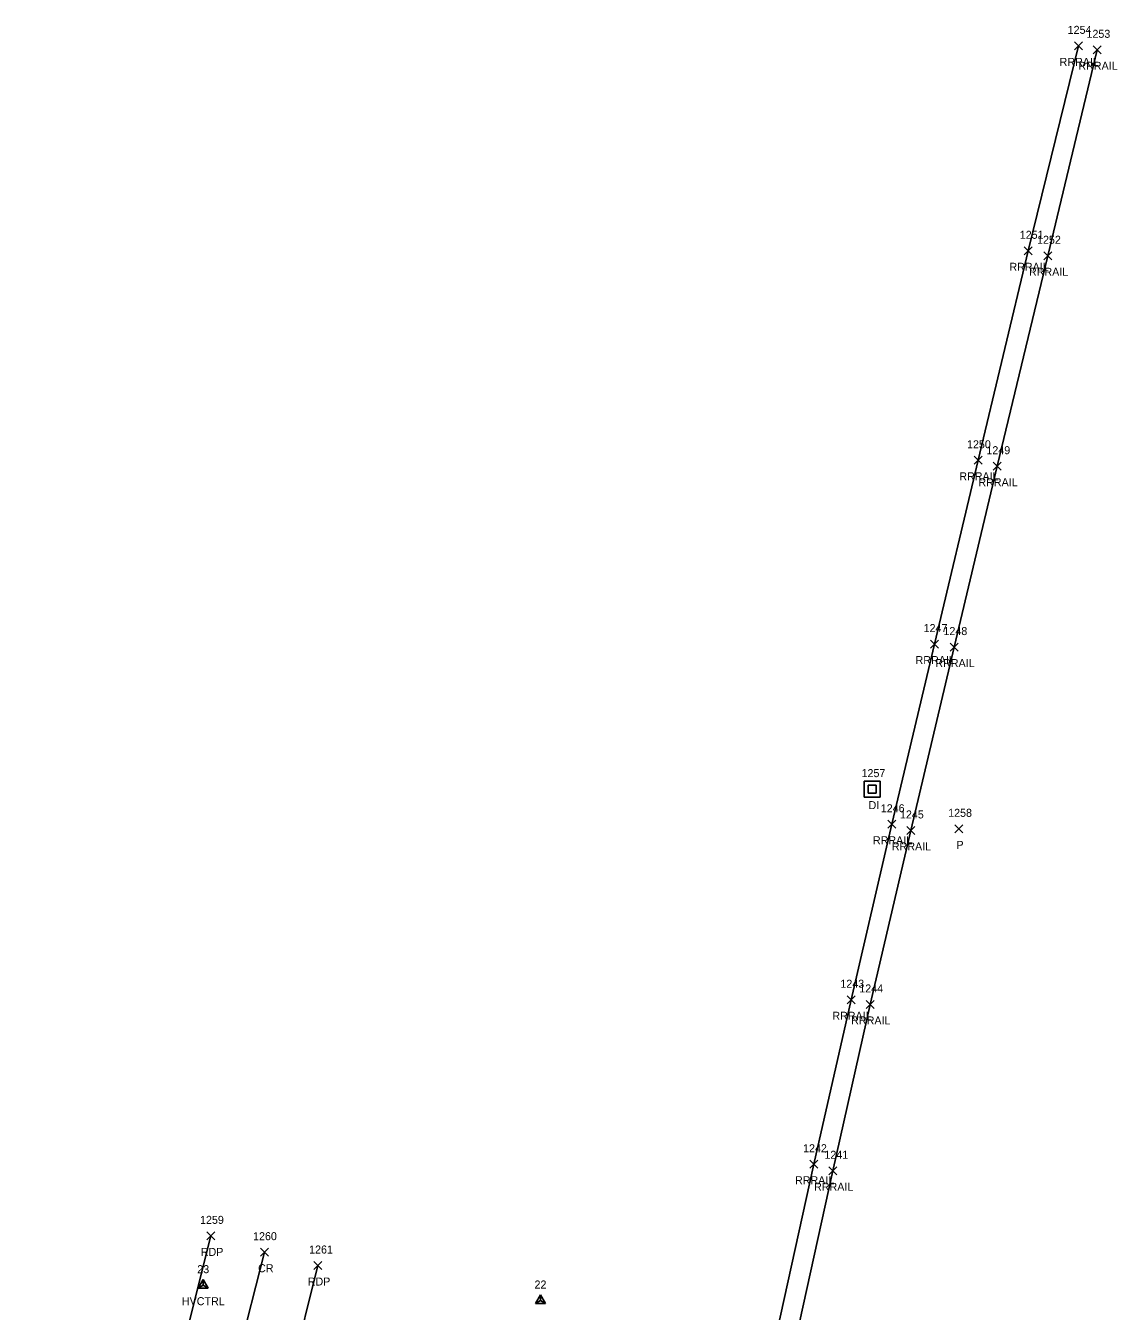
# Model space of a CAD drawing. Extents: x 1754529 to 1755810, y 621660 to 624656.
# Drawn here: x 1755537 to 1755809.8, y 624334.6 to 624655.8 of the extents above; entities that cross this region are included whole.
import ezdxf

# ---------------------------------------------------------------- set-up
doc = ezdxf.new("R2010")
doc.units = 0
for name, color, linetype in [('C_A', 7, 'Continuous'), ('C_I', 7, 'Continuous'), ('CPSM', 7, 'Continuous'), ('D_A', 7, 'Continuous'), ('D_I', 7, 'Continuous'), ('D_TIC', 7, 'Continuous'), ('DS', 7, 'Continuous'), ('Level 14', 7, 'Continuous'), ('P_A', 7, 'Continuous'), ('P_I', 7, 'Continuous'), ('PET', 7, 'Continuous'), ('PRC', 7, 'Continuous'), ('R_A', 7, 'Continuous'), ('R_I', 7, 'Continuous'), ('R_TIC', 7, 'Continuous'), ('RR', 7, 'Continuous')]:
    doc.layers.add(name, color=color, linetype=linetype)

msp = doc.modelspace()

# ---------------------------------------------------------------- linework, layer by layer
at = {"layer": 'CPSM'}
for p, q in [((1755580.07, 624340.36), (1755581.32, 624342.53)), ((1755582.57, 624340.36), (1755581.32, 624342.53)), ((1755581.32, 624341.08), (1755581.32, 624342.53)), ((1755580.07, 624340.36), (1755581.32, 624341.08)), ((1755580.07, 624340.36), (1755582.57, 624340.36)), ((1755581.32, 624341.08), (1755581.32, 624341.08)), ((1755581.32, 624341.08), (1755582.57, 624340.36)), ((1755664.34, 624336.53), (1755665.59, 624338.69)), ((1755664.34, 624336.53), (1755665.59, 624337.25)), ((1755664.34, 624336.53), (1755666.84, 624336.53)), ((1755666.84, 624336.53), (1755665.59, 624338.69)), ((1755665.59, 624337.25), (1755665.59, 624338.69)), ((1755665.59, 624337.25), (1755665.59, 624337.25)), ((1755665.59, 624337.25), (1755666.84, 624336.53))]:
    msp.add_line(p, q, dxfattribs=at)
at = {"layer": 'D_TIC'}
for points in [[(1755769.2, 624454.1), (1755771.2, 624456.1)], [(1755771.2, 624454.1), (1755769.2, 624456.1)]]:
    msp.add_lwpolyline(points, dxfattribs=at)
at = {"layer": 'DS'}
for p, q in [((1755746.54, 624467.02), (1755750.54, 624467.02)), ((1755746.54, 624463.02), (1755746.54, 624467.02)), ((1755747.54, 624464.02), (1755747.54, 624466.02)), ((1755747.54, 624466.02), (1755749.54, 624466.02)), ((1755748.54, 624465.02), (1755748.54, 624465.02)), ((1755748.54, 624465.02), (1755748.54, 624465.02)), ((1755749.54, 624466.02), (1755749.54, 624464.02)), ((1755750.54, 624467.02), (1755750.54, 624463.02)), ((1755750.54, 624463.02), (1755746.54, 624463.02)), ((1755749.54, 624464.02), (1755747.54, 624464.02))]:
    msp.add_line(p, q, dxfattribs=at)
at = {"layer": 'Level 14'}
for points in [[(1755582.24, 624352.4), (1755584.24, 624354.4)], [(1755584.24, 624352.4), (1755582.24, 624354.4)], [(1755595.62, 624348.32), (1755597.62, 624350.32)], [(1755597.62, 624348.32), (1755595.62, 624350.32)], [(1755608.98, 624344.99), (1755610.98, 624346.99)], [(1755610.98, 624344.99), (1755608.98, 624346.99)]]:
    msp.add_lwpolyline(points, dxfattribs=at)
at = {"layer": 'PET'}
for points in [[(1755583.24, 624353.4), (1755570.27, 624301.63), (1755560.22, 624258.14), (1755548.1, 624200.26), (1755536.97, 624143.24)], [(1755609.98, 624345.99), (1755597.12, 624294.33), (1755586.94, 624249.39), (1755575.43, 624196.55), (1755564.19, 624138.53)]]:
    msp.add_lwpolyline(points, dxfattribs=at)
at = {"layer": 'PRC'}
msp.add_lwpolyline([(1755596.62, 624349.32), (1755583.45, 624297.71), (1755573.49, 624253.54), (1755562.13, 624198.27), (1755550.9, 624141.51)], dxfattribs=at)
at = {"layer": 'R_TIC'}
for points in [[(1755799.05, 624649.73), (1755801.05, 624651.73)], [(1755801.05, 624649.73), (1755799.05, 624651.73)], [(1755803.75, 624648.74), (1755805.75, 624650.74)], [(1755805.75, 624648.74), (1755803.75, 624650.74)], [(1755786.52, 624598.52), (1755788.52, 624600.52)], [(1755788.52, 624598.52), (1755786.52, 624600.52)], [(1755791.4, 624597.28), (1755793.4, 624599.28)], [(1755793.4, 624597.28), (1755791.4, 624599.28)], [(1755773.99, 624546.18), (1755775.99, 624548.18)], [(1755775.99, 624546.18), (1755773.99, 624548.18)], [(1755778.76, 624544.7), (1755780.76, 624546.7)], [(1755780.76, 624544.7), (1755778.76, 624546.7)], [(1755763.06, 624500.26), (1755765.06, 624502.26)], [(1755765.06, 624500.26), (1755763.06, 624502.26)], [(1755768.01, 624499.51), (1755770.01, 624501.51)], [(1755770.01, 624499.51), (1755768.01, 624501.51)], [(1755752.41, 624455.24), (1755754.41, 624457.24)], [(1755754.41, 624455.24), (1755752.41, 624457.24)], [(1755757.14, 624453.7), (1755759.14, 624455.7)], [(1755759.14, 624453.7), (1755757.14, 624455.7)], [(1755742.26, 624411.4), (1755744.26, 624413.4)], [(1755744.26, 624411.4), (1755742.26, 624413.4)], [(1755746.98, 624410.22), (1755748.98, 624412.22)], [(1755748.98, 624410.22), (1755746.98, 624412.22)], [(1755732.93, 624370.3), (1755734.93, 624372.3)], [(1755734.93, 624370.3), (1755732.93, 624372.3)], [(1755737.69, 624368.66), (1755739.69, 624370.66)], [(1755739.69, 624368.66), (1755737.69, 624370.66)]]:
    msp.add_lwpolyline(points, dxfattribs=at)
at = {"layer": 'RR'}
for points in [[(1755627.39, 623699.11), (1755631.78, 623745.19), (1755637.11, 623795.68), (1755642.45, 623841.98), (1755647.89, 623885.58), (1755654.04, 623931.54), (1755660.61, 623977.9), (1755666.29, 624016.06), (1755672.3, 624053.9), (1755679.64, 624097.76), (1755687.07, 624139.84), (1755694.5, 624180.62), (1755701.72, 624217.85), (1755709.31, 624256.23), (1755717.86, 624297.53), (1755724.56, 624328.91), (1755733.93, 624371.3), (1755743.26, 624412.4), (1755753.41, 624456.24), (1755764.06, 624501.26), (1755774.99, 624547.18), (1755787.52, 624599.52), (1755800.05, 624650.73)], [(1755632.43, 623698.79), (1755636.73, 623745.2), (1755642.03, 623795.46), (1755647.4, 623842), (1755652.81, 623884.87), (1755658.94, 623931.22), (1755665.5, 623977.61), (1755671.13, 624015.19), (1755677.17, 624053.23), (1755684.42, 624096.54), (1755692.03, 624139.27), (1755699.47, 624179.9), (1755706.47, 624216.55), (1755714.07, 624254.59), (1755722.62, 624295.88), (1755729.35, 624327.29), (1755738.69, 624369.66), (1755747.98, 624411.22), (1755758.14, 624454.7), (1755769.01, 624500.51), (1755779.76, 624545.7), (1755792.4, 624598.28), (1755804.75, 624649.74)]]:
    msp.add_lwpolyline(points, dxfattribs=at)

# ---------------------------------------------------------------- texts
at = {"layer": 'C_A'}
msp.add_text('HVCTRL', height=2, dxfattribs=at).set_placement((1755576.01, 624336.08))
at = {"layer": 'C_I'}
for s, p in [('23', (1755579.85, 624344.08)), ('22', (1755664.13, 624340.25))]:
    msp.add_text(s, height=2, dxfattribs=at).set_placement(p)
at = {"layer": 'D_A'}
for s, p in [('DI', (1755747.6, 624460.02)), ('P', (1755769.57, 624450.1))]:
    msp.add_text(s, height=2, dxfattribs=at).set_placement(p)
at = {"layer": 'D_I'}
for s, p in [('1257', (1755745.85, 624468.02)), ('1258', (1755767.5, 624458.1))]:
    msp.add_text(s, height=2, dxfattribs=at).set_placement(p)
at = {"layer": 'P_A'}
for s, p in [('RDP', (1755580.73, 624348.4)), ('CR', (1755595.05, 624344.32)), ('RDP', (1755607.46, 624340.99))]:
    msp.add_text(s, height=2, dxfattribs=at).set_placement(p)
at = {"layer": 'P_I'}
for s, p in [('1259', (1755580.54, 624356.4)), ('1260', (1755593.79, 624352.32)), ('1261', (1755607.8, 624348.99))]:
    msp.add_text(s, height=2, dxfattribs=at).set_placement(p)
at = {"layer": 'R_A'}
for p in [(1755795.34, 624645.73), (1755800.04, 624644.74), (1755782.81, 624594.52), (1755787.69, 624593.28), (1755770.28, 624542.18), (1755775.05, 624540.7), (1755759.35, 624496.26), (1755764.3, 624495.51), (1755748.7, 624451.24), (1755753.43, 624449.7), (1755738.55, 624407.4), (1755743.27, 624406.22), (1755729.22, 624366.3), (1755733.99, 624364.66)]:
    msp.add_text('RRRAIL', height=2, dxfattribs=at).set_placement(p)
at = {"layer": 'R_I'}
for s, p in [('1254', (1755797.36, 624653.73)), ('1253', (1755802.06, 624652.74)), ('1251', (1755785.39, 624602.52)), ('1252', (1755789.71, 624601.28)), ('1250', (1755772.21, 624550.18)), ('1249', (1755777.05, 624548.7)), ('1247', (1755761.36, 624504.26)), ('1248', (1755766.32, 624503.51)), ('1246', (1755750.66, 624459.24)), ('1245', (1755755.45, 624457.7)), ('1243', (1755740.56, 624415.4)), ('1244', (1755745.29, 624414.22)), ('1242', (1755731.24, 624374.3)), ('1241', (1755736.57, 624372.66))]:
    msp.add_text(s, height=2, dxfattribs=at).set_placement(p)

doc.saveas('drawing.dxf')
